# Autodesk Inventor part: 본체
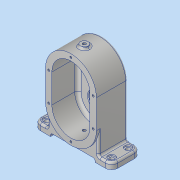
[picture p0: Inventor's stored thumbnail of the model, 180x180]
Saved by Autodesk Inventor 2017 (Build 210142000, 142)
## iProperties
Part Number: 본체
Material: 알루미늄 6061
Document SubType Name: Modeling
Designer: MRC
Density: 2.7 g/cm^3
Appearance: 알루미늄 - 평지
Mass: 756.754 g
Surface Area: 581.829 cm^2
Volume: 280.279 cm^3
Author: MRC
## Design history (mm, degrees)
sketch "스케치1"
  geometry: L1 (0, 0)-(0, 45); L2 (-40, 0)-(-40, 45); L3 (40, 45)-(40, 0); A1 r 40 centre (0, 0) between (-40, 0) and (40, 0); A2 r 40 centre (0, 45) between (40, 45) and (-40, 45); 1 further point
  constraints: 8 end point, 4 point on circle, 4 tangent, 2 centre point, 1 midpoint, 1 parallel, 1 vertical
  dimensions: "d0" = 45 distance of L1.start L1.end; "d1" = 80 distance between parallel lines of L3 L2
extrude "돌출1" new body sketch "스케치1" stored distance "d2" = 49; taper "d3" = 0 deg
sketch "스케치2"
  geometry: L1 (0, 45)-(0, 0); L2 (-26, 45)-(-26, 0); L3 (26, 0)-(26, 45); A1 r 40 centre (0, 45) between (40, 45) and (-40, 45) reference; A2 r 40 centre (0, 0) between (-40, 0) and (40, 0) reference; A3 r 26 centre (0, 45) between (26, 45) and (-26, 45); A4 r 26 centre (0, 0) between (-26, 0) and (26, 0); 1 further point
  constraints: 8 end point, 4 point on circle, 4 tangent, 2 centre point, 1 midpoint, 1 parallel, 1 vertical
  dimensions: "d4" = 52 distance between parallel lines of L3 L2
extrude "돌출2" join sketch "스케치2" distance "d5" = 8; taper "d6" = 0 deg
sketch "스케치3"
  geometry: L1 (0, 0)-(0, 45); L2 (-26, 0)-(-26, 15); L3 (26, 15)-(26, 0); L4 (-26, 0)-(-26, 45) reference; L5 (-26, 15)-(26, 15); L6 (26, 45)-(26, 0) reference; A1 r 26 centre (0, 0) between (-26, 0) and (26, 0) reference; A2 r 26 centre (0, 0) between (-26, 0) and (26, 0); 1 further point
  constraints: 10 end point, 2 point on circle, 2 point on line, 2 tangent, 1 centre point, 1 midpoint, 1 parallel, 1 vertical
  dimensions: "d7" = 30 distance from line of L1.end L5; "d8" = 52 distance of L2.end L3.start
extrude "돌출3" join sketch "스케치3" distance "d9" = 3; taper "d10" = 0 deg
node "작업 평면1"
sketch "스케치4"
  geometry: L1 (40, 24.5)-(-40, 24.5) reference; C1 r 6 at (0, 3.5); 1 further point
  constraints: 1 centre point, 1 vertical alignment
  dimensions: "d12" = 12 diameter of C1; "d14" = 21 distance from line of L1 C1.centre
extrude "돌출4" join sketch "스케치4" stored distance "d15" = 3; taper "d16" = 0 deg
sketch "스케치6"
  geometry: L1 (-40, 45)-(-40, 0) reference; L2 (40, 0)-(40, 45) reference; L3 (-30, 45)-(-30, 0); L4 (30, 0)-(30, 45); A1 r 40 centre (0, 0) between (-40, 0) and (40, 0) reference; A2 r 40 centre (0, 45) between (40, 45) and (-40, 45) reference; A3 r 30 centre (0, 0) between (-30, 0) and (30, 0); A4 r 30 centre (0, 45) between (30, 45) and (-30, 45)
  constraints: 4 end point, 4 point on circle, 2 centre point, 3 other
  dimensions: "d22" = 30 radius of A4
extrude "돌출5" cut sketch "스케치6" distance "d23" = 41; taper "d24" = 0 deg
hole "구멍1" diameter "d27" = 22; stored, may be unused: countersink angle "d31" = 90 deg, drill point angle "d33" = 118 deg; dims "d25" = 10, "d26" = 10, "d28" = 6, "d29" = 28, "d30" = 8, "d32" = 8
hole "구멍2" diameter "d36" = 20; stored, may be unused: countersink angle "d40" = 90 deg, drill point angle "d42" = 0 deg; dims "d34" = 10, "d35" = 10, "d37" = 6, "d38" = 28, "d39" = 8, "d41" = 12
sketch "스케치7"
  geometry: C1 r 11 at (0, 45) reference; C2 r 14 at (0, 45); A1 r 26 centre (0, 45) between (26, 45) and (-26, 45) reference; 1 further point
  constraints: 1 centre point, 1 coincident
  dimensions: "d43" = 28 diameter of C2
extrude "돌출6" cut sketch "스케치7" distance "d44" = 4; taper "d45" = 0 deg
sketch "스케치8"
  geometry: C1 r 14 at (0, 45) reference; A1 r 40 centre (0, 45) between (40, 45) and (-40, 45) reference; 2 further points
  constraints: 1 vertical alignment
  dimensions: "d46" = 20 distance of A1.centre point (0, 65)
hole "구멍3" sketch "스케치8" at (0, 65) diameter "d47" = 3.242; stored, may be unused: countersink angle "d51" = 90 deg, drill point angle "d53" = 118 deg; dims "d48" = 8, "d49" = 28, "d50" = 8, "d52" = 10
hole "구멍4" diameter "d59" = 4.917; stored, may be unused: countersink angle "d63" = 90 deg, drill point angle "d65" = 118 deg; dims "d57" = 10, "d58" = 10, "d60" = 12, "d61" = 28, "d62" = 8, "d64" = 17.1
sketch "스케치9"
  geometry: L1 (40, 0)-(40, 45) reference; L2 (-40, 45)-(-40, 0) reference; L3 (-40, 0)-(-40, -37); L4 (-40, -37)-(-61, -37); L5 (-61, -37)-(-61, -47); L6 (-61, -47)-(-35, -47); L7 (-35, -47)-(-35, -42); L8 (-35, -42)-(35, -42); L9 (35, -42)-(35, -47); L10 (35, -47)-(61, -47); L11 (61, -47)-(61, -37); L12 (61, -37)-(40, -37); L13 (40, -37)-(40, 0); A1 r 26 centre (0, 0) between (-26, 0) and (26, 0) reference; A2 r 40 centre (0, 0) between (-40, 0) and (40, 0) reference
  constraints: 22 end point, 8 perpendicular, 4 collinear, 4 point on line, 2 point on circle, 1 vertical
  dimensions: "d66" = 70 distance of L7.end L8.end; "d67" = 47 distance from line of L6 A1.centre; "d68" = 10 distance of L4.end L5.end; "d69" = 5 distance of L6.end L7.end; "d70" = 122 distance between parallel lines of L11 L5
extrude "돌출7" join sketch "스케치9" distance "d71" = 46; taper "d72" = 0 deg
fillet "모깎기1" dims "d73" = 10
hole "구멍5" diameter "d76" = 6.6; stored, may be unused: countersink angle "d80" = 90 deg, drill point angle "d82" = 118 deg; dims "d74" = 10, "d75" = 10, "d77" = 12, "d78" = 11, "d79" = 2, "d81" = 17.1
hole "구멍6" diameter "d85" = 6.6; stored, may be unused: countersink angle "d89" = 90 deg, drill point angle "d91" = 118 deg; dims "d83" = 10, "d84" = 10, "d86" = 12, "d87" = 11, "d88" = 2, "d90" = 17.1
hole "구멍7" diameter "d94" = 6.6; stored, may be unused: countersink angle "d98" = 90 deg, drill point angle "d100" = 118 deg; dims "d92" = 10, "d93" = 10, "d95" = 12, "d96" = 11, "d97" = 2, "d99" = 17.1
hole "구멍8" diameter "d103" = 6.6; stored, may be unused: countersink angle "d107" = 90 deg, drill point angle "d109" = 118 deg; dims "d101" = 10, "d102" = 10, "d104" = 12, "d105" = 11, "d106" = 2, "d108" = 17.1
sketch "스케치10"
  geometry: L1 (75, 49)-(-5, 49) reference; 2 further points
  constraints: 1 vertical alignment
  dimensions: "d110" = 21 distance from line of point (35, 28) L1
hole "구멍9" sketch "스케치10" at (35, 28) diameter "d111" = 4.917; stored, may be unused: countersink angle "d115" = 90 deg, drill point angle "d117" = 118 deg; dims "d112" = 12, "d113" = 12, "d114" = 1, "d116" = 17.1
sketch "스케치11"
  geometry: L1 (-30, 0)-(-30, 45) reference; L2 (30, 45)-(30, 0) reference; L3 (-35, 45)-(-35, 0); L4 (35, 0)-(35, 45); A1 r 30 centre (0, 0) between (-30, 0) and (30, 0) reference; A2 r 30 centre (0, 45) between (30, 45) and (-30, 45) reference; A3 r 35 centre (0, 0) between (-35, 0) and (35, 0); A4 r 35 centre (0, 45) between (35, 45) and (-35, 45); 6 further points
  constraints: 6 point on circle, 4 coincident, 4 end point, 2 centre point, 3 other
  dimensions: "d118" = 35 radius of A4
hole "구멍10" sketch "스케치11" at (0, 80), (35, 45), (-35, 45), (-35, 0), (0, -35), (35, 0) diameter "d119" = 3.242; stored, may be unused: countersink angle "d123" = 90 deg, drill point angle "d125" = 118 deg; dims "d120" = 8, "d121" = 12, "d122" = 1, "d124" = 10
chamfer "모따기1" distance "d126" = 1; stored, may be unused: second distance "d127" = 2, angle "d128" = 45 deg
fillet "모깎기2" dims "d129" = 3
fillet "모깎기3" dims "d130" = 3
fillet "모깎기4" dims "d131" = 5
sketch "스케치12"
  geometry: L1 (-51, -47)-(-61, -47) reference; A1 r 37 centre (0, 45) between (37, 45) and (-37, 45) reference; 1 further point
  constraints: 1 vertical alignment, 1 other
  dimensions: "d132" = 12 distance from line of point (0, -35) L1
feature "엠보싱1" sketch "스케치12" dims "d0" = 45, "d1" = 80, "d133" = 0.5, "d134" = 0
fillet "모깎기5" dims "d135" = 0.3
node "솔리드1"
pattern_circular "원형 패턴1" dims angle "d55" = 360 deg
other parameters: "d11" = 88
